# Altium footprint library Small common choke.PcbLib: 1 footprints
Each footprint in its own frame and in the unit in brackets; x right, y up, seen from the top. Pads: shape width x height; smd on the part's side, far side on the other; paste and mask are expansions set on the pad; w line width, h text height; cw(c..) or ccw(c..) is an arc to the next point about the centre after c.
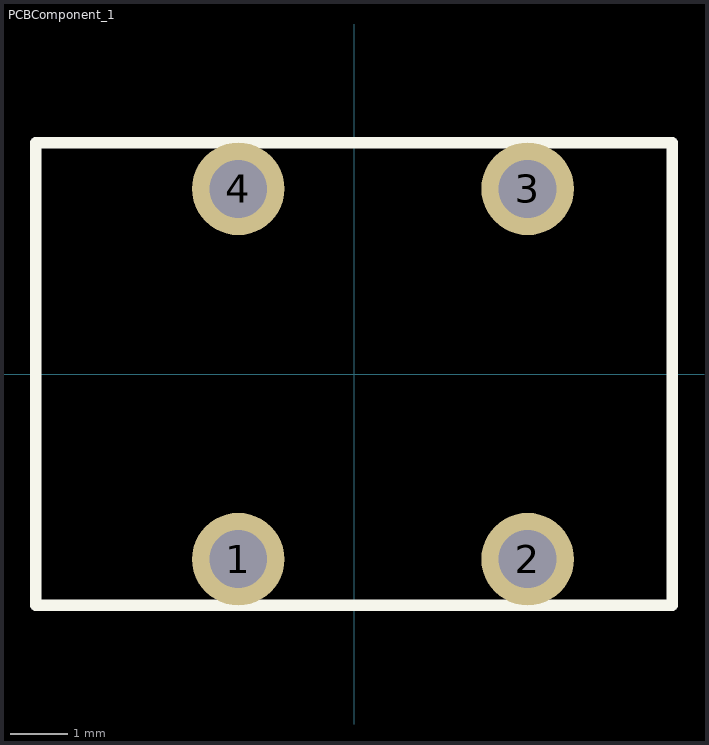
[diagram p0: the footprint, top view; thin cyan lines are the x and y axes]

## PCBComponent_1 [mm]
pads (4):
  round 1.6 hole 1: 1(-2,-3.2) 2(3,-3.2) 3(3,3.2) 4(-2,3.2)
Top Overlay:
  lines w0.2: -5.5,-4 5.5,-4 5.5,4 -5.5,4 -5.5,-4
M5 Assembly Top:
  text ".Designator" at -2,-0.7 h1.85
